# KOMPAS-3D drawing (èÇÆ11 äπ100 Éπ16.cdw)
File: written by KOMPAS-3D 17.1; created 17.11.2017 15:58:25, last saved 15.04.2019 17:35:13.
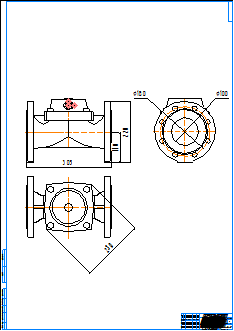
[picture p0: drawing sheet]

Sheet 1: A0, portrait

Title block, sheet 1: name: КАТ11 Ду100 Ру16; material: Внимание! Данный продукт является объектом авторского права ООО «Торговый Дом АДЛ». / Запрещается изменение, копирование, распространение / (в том числе путем копирования на другие сайты и ресурсы в Интернете) / или любое иное использование информации и объектов без предварительного / согласия правообладателя (ООО «Торговый Дом АДЛ»).; mass: 12,4; sheets: 1; organisation: ООО "Торговый дом АДЛ"; sheet format: A0; stored path: \\adlc.lan\data\АДЛ_ПКД\3D-модели\ADL production\Клапаны КАТ ГРАНРЕГ\КАТ11\KOMPAS 2D\КАТ11 Ду100 Ру16.cdw

Views: Вид 1, Проекционный вид 2, Проекционный вид 3
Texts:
  kka
  adl
Dimensions and other numbers on the sheet: 305; 110; 220; 180; 100; 230; 1:1; 1; 12,4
